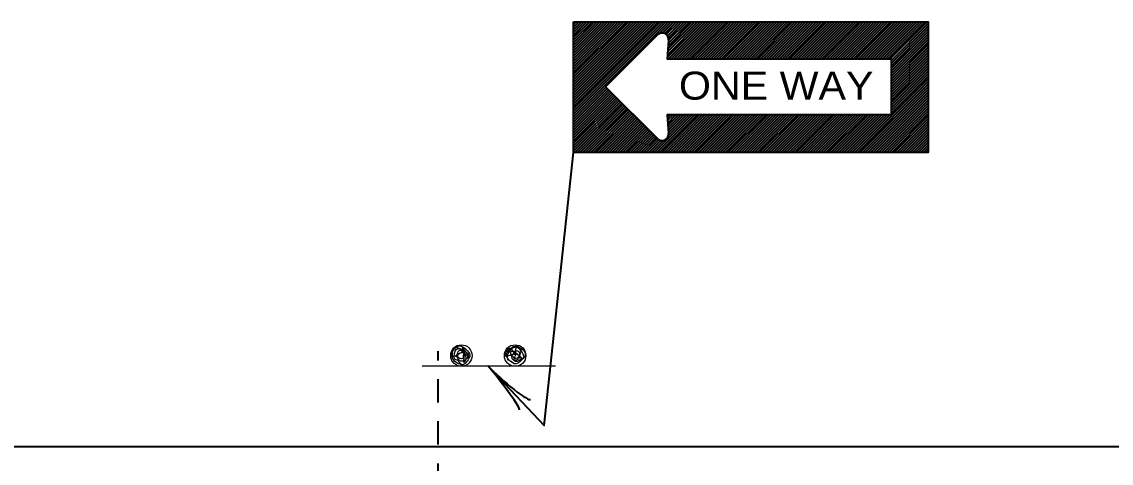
# Model space of a CAD drawing. Extents: x 1081 to 1936, y -630 to -24.
# Drawn here: x 1299 to 1369, y -188.8 to -160.5 of the extents above; entities that cross this region are included whole.
import ezdxf
from ezdxf.enums import TextEntityAlignment as Align

# ---------------------------------------------------------------- set-up
doc = ezdxf.new("R2010")
doc.units = 0
doc.linetypes.add('SHORT_DASHED', pattern=[2.7, 1.5, -1.2])
doc.layers.add('1', color=7, linetype='Continuous', lineweight=53)
doc.layers.add('4', color=7, linetype='Continuous', lineweight=25)

msp = doc.modelspace()

# ---------------------------------------------------------------- linework, layer by layer
at = {"layer": '1', "lineweight": 35}
for p, q in [((1334.418, -160.454), (1334.42, -160.453)), ((1334.418, -160.624), (1334.589, -160.453)), ((1334.418, -160.794), (1334.759, -160.453)), ((1334.418, -160.963), (1334.929, -160.453)), ((1334.418, -161.133), (1335.099, -160.453)), ((1334.418, -161.303), (1335.268, -160.453)), ((1334.418, -161.472), (1335.438, -160.453)), ((1334.418, -161.642), (1335.608, -160.453)), ((1334.418, -161.812), (1335.777, -160.453)), ((1334.418, -161.982), (1335.947, -160.453)), ((1334.418, -162.151), (1336.117, -160.453)), ((1334.418, -162.321), (1336.286, -160.453)), ((1334.418, -162.491), (1336.456, -160.453)), ((1334.418, -162.66), (1336.626, -160.453)), ((1334.418, -162.83), (1336.796, -160.453)), ((1334.418, -163), (1336.965, -160.453)), ((1334.418, -163.169), (1337.135, -160.453)), ((1334.418, -163.339), (1337.305, -160.453)), ((1334.418, -163.509), (1337.474, -160.453)), ((1334.418, -163.679), (1337.644, -160.453)), ((1334.418, -163.848), (1337.814, -160.453)), ((1334.418, -164.018), (1337.984, -160.453)), ((1334.418, -164.188), (1338.153, -160.453)), ((1334.418, -164.357), (1338.323, -160.453)), ((1334.418, -164.527), (1338.493, -160.453)), ((1334.418, -164.697), (1338.662, -160.453)), ((1334.418, -164.867), (1338.832, -160.453)), ((1334.418, -165.036), (1339.002, -160.453)), ((1334.418, -165.206), (1339.171, -160.453)), ((1334.418, -165.376), (1339.341, -160.453)), ((1334.418, -165.545), (1339.511, -160.453)), ((1334.418, -165.715), (1339.681, -160.453)), ((1334.418, -165.885), (1339.85, -160.453)), ((1334.418, -166.054), (1340.02, -160.453)), ((1334.418, -166.224), (1340.19, -160.453)), ((1334.418, -166.394), (1340.359, -160.453)), ((1334.418, -166.564), (1340.529, -160.453)), ((1339.953, -161.198), (1340.699, -160.453)), ((1340.145, -161.176), (1340.869, -160.453)), ((1340.278, -161.213), (1341.038, -160.453)), ((1340.382, -161.278), (1341.208, -160.453)), ((1340.436, -162.752), (1342.735, -160.453)), ((1340.452, -162.566), (1342.566, -160.453)), ((1340.461, -161.369), (1341.378, -160.453)), ((1340.469, -162.38), (1342.396, -160.453)), ((1340.485, -162.194), (1342.226, -160.453)), ((1340.501, -162.008), (1342.056, -160.453)), ((1340.516, -161.484), (1341.547, -160.453)), ((1340.518, -161.822), (1341.887, -160.453)), ((1340.527, -162.831), (1342.905, -160.453)), ((1340.534, -161.636), (1341.717, -160.453)), ((1340.697, -162.831), (1343.075, -160.453)), ((1340.866, -162.831), (1343.244, -160.453)), ((1341.036, -162.831), (1343.414, -160.453)), ((1341.206, -162.831), (1343.584, -160.453)), ((1341.375, -162.831), (1343.754, -160.453)), ((1341.545, -162.831), (1343.923, -160.453)), ((1341.715, -162.831), (1344.093, -160.453)), ((1341.885, -162.831), (1344.263, -160.453)), ((1342.054, -162.831), (1344.432, -160.453)), ((1342.224, -162.831), (1344.602, -160.453)), ((1342.394, -162.831), (1344.772, -160.453)), ((1342.563, -162.831), (1344.941, -160.453)), ((1342.733, -162.831), (1345.111, -160.453)), ((1342.903, -162.831), (1345.281, -160.453)), ((1343.072, -162.831), (1345.451, -160.453)), ((1343.242, -162.831), (1345.62, -160.453)), ((1343.412, -162.831), (1345.79, -160.453)), ((1343.582, -162.831), (1345.96, -160.453)), ((1343.751, -162.831), (1346.129, -160.453)), ((1343.921, -162.831), (1346.299, -160.453)), ((1344.091, -162.831), (1346.469, -160.453)), ((1344.26, -162.831), (1346.639, -160.453)), ((1344.43, -162.831), (1346.808, -160.453)), ((1344.6, -162.831), (1346.978, -160.453)), ((1344.77, -162.831), (1347.148, -160.453)), ((1344.939, -162.831), (1347.317, -160.453)), ((1345.109, -162.831), (1347.487, -160.453)), ((1345.279, -162.831), (1347.657, -160.453)), ((1345.448, -162.831), (1347.826, -160.453)), ((1345.618, -162.831), (1347.996, -160.453)), ((1345.788, -162.831), (1348.166, -160.453)), ((1345.957, -162.831), (1348.336, -160.453)), ((1346.127, -162.831), (1348.505, -160.453)), ((1346.297, -162.831), (1348.675, -160.453)), ((1346.466, -162.831), (1348.845, -160.453)), ((1346.636, -162.831), (1349.014, -160.453)), ((1346.806, -162.831), (1349.184, -160.453)), ((1346.976, -162.831), (1349.354, -160.453)), ((1347.145, -162.831), (1349.524, -160.453)), ((1347.315, -162.831), (1349.693, -160.453)), ((1347.485, -162.831), (1349.863, -160.453)), ((1347.655, -162.831), (1350.033, -160.453)), ((1347.824, -162.831), (1350.202, -160.453)), ((1347.994, -162.831), (1350.372, -160.453)), ((1348.164, -162.831), (1350.542, -160.453)), ((1348.333, -162.831), (1350.711, -160.453)), ((1348.503, -162.831), (1350.881, -160.453)), ((1348.673, -162.831), (1351.051, -160.453)), ((1348.842, -162.831), (1351.221, -160.453)), ((1349.012, -162.831), (1351.39, -160.453)), ((1349.182, -162.831), (1351.56, -160.453)), ((1349.351, -162.831), (1351.73, -160.453)), ((1349.521, -162.831), (1351.899, -160.453)), ((1349.691, -162.831), (1352.069, -160.453)), ((1349.861, -162.831), (1352.239, -160.453)), ((1350.03, -162.831), (1352.409, -160.453)), ((1350.2, -162.831), (1352.578, -160.453)), ((1350.37, -162.831), (1352.748, -160.453)), ((1350.54, -162.831), (1352.918, -160.453)), ((1350.709, -162.831), (1353.087, -160.453)), ((1350.879, -162.831), (1353.257, -160.453)), ((1351.049, -162.831), (1353.427, -160.453)), ((1351.218, -162.831), (1353.596, -160.453)), ((1351.388, -162.831), (1353.766, -160.453)), ((1351.558, -162.831), (1353.936, -160.453)), ((1351.727, -162.831), (1354.106, -160.453)), ((1351.897, -162.831), (1354.275, -160.453)), ((1352.067, -162.831), (1354.445, -160.453)), ((1352.236, -162.831), (1354.615, -160.453)), ((1352.406, -162.831), (1354.784, -160.453)), ((1352.576, -162.831), (1354.954, -160.453)), ((1352.746, -162.831), (1355.124, -160.453)), ((1352.915, -162.831), (1355.293, -160.453)), ((1353.085, -162.831), (1355.463, -160.453)), ((1353.255, -162.831), (1355.633, -160.453)), ((1353.425, -162.831), (1355.803, -160.453)), ((1353.594, -162.831), (1355.972, -160.453)), ((1353.764, -162.831), (1356.142, -160.453)), ((1353.934, -162.831), (1356.312, -160.453)), ((1354.103, -162.831), (1356.481, -160.453)), ((1354.273, -162.831), (1356.651, -160.453)), ((1354.443, -162.831), (1356.821, -160.453)), ((1354.612, -162.831), (1356.991, -160.453)), ((1354.782, -162.831), (1357.16, -160.453)), ((1354.829, -162.953), (1357.218, -160.564)), ((1354.829, -163.123), (1357.218, -160.734)), ((1354.829, -163.293), (1357.218, -160.904)), ((1336.478, -164.631), (1339.872, -161.236)), ((1354.829, -163.462), (1357.218, -161.073)), ((1354.829, -163.632), (1357.218, -161.243)), ((1354.829, -163.802), (1357.218, -161.413)), ((1354.829, -163.972), (1357.218, -161.583)), ((1354.829, -164.141), (1357.218, -161.752)), ((1354.829, -164.311), (1357.218, -161.922)), ((1354.829, -164.481), (1357.218, -162.092)), ((1354.829, -164.65), (1357.218, -162.262)), ((1354.829, -164.82), (1357.218, -162.431)), ((1354.829, -164.99), (1357.218, -162.601)), ((1354.829, -165.159), (1357.218, -162.771)), ((1354.829, -165.329), (1357.218, -162.94)), ((1354.829, -165.499), (1357.218, -163.11)), ((1354.829, -165.668), (1357.218, -163.28)), ((1354.829, -165.838), (1357.218, -163.449)), ((1354.829, -166.008), (1357.218, -163.619)), ((1354.829, -166.178), (1357.218, -163.789)), ((1352.494, -168.853), (1357.218, -164.128)), ((1352.663, -168.853), (1357.218, -164.298)), ((1352.833, -168.853), (1357.218, -164.468)), ((1354.829, -166.347), (1357.218, -163.959)), ((1334.418, -166.733), (1336.499, -164.652)), ((1334.418, -166.903), (1336.584, -164.737)), ((1334.418, -167.073), (1336.669, -164.822)), ((1334.418, -167.242), (1336.754, -164.907)), ((1334.418, -167.412), (1336.839, -164.992)), ((1334.418, -167.582), (1336.923, -165.076)), ((1334.418, -167.752), (1337.008, -165.161)), ((1334.418, -167.921), (1337.093, -165.246)), ((1339.872, -168.025), (1336.478, -164.631)), ((1353.003, -168.853), (1357.218, -164.637)), ((1353.173, -168.853), (1357.218, -164.807)), ((1353.342, -168.853), (1357.218, -164.977)), ((1353.512, -168.853), (1357.218, -165.147)), ((1334.418, -168.091), (1337.178, -165.331)), ((1334.418, -168.261), (1337.263, -165.416)), ((1334.418, -168.43), (1337.348, -165.501)), ((1334.418, -168.6), (1337.433, -165.585)), ((1334.418, -168.77), (1337.517, -165.67)), ((1334.505, -168.853), (1337.602, -165.755)), ((1334.675, -168.853), (1337.687, -165.84)), ((1334.844, -168.853), (1337.772, -165.925)), ((1353.682, -168.853), (1357.218, -165.316)), ((1353.851, -168.853), (1357.218, -165.486)), ((1354.021, -168.853), (1357.218, -165.656)), ((1354.191, -168.853), (1357.218, -165.825)), ((1335.014, -168.853), (1337.857, -166.01)), ((1335.184, -168.853), (1337.942, -166.095)), ((1335.354, -168.853), (1338.027, -166.179)), ((1335.523, -168.853), (1338.111, -166.264)), ((1335.693, -168.853), (1338.196, -166.349)), ((1335.863, -168.853), (1338.281, -166.434)), ((1336.032, -168.853), (1338.366, -166.519)), ((1336.202, -168.853), (1338.451, -166.604)), ((1339.596, -168.853), (1342.018, -166.431)), ((1339.766, -168.853), (1342.188, -166.431)), ((1339.936, -168.853), (1342.357, -166.431)), ((1340.105, -168.853), (1342.527, -166.431)), ((1340.275, -168.853), (1342.697, -166.431)), ((1340.434, -166.487), (1340.491, -166.431)), ((1340.445, -168.853), (1342.867, -166.431)), ((1340.448, -166.643), (1340.66, -166.431)), ((1340.462, -166.799), (1340.83, -166.431)), ((1340.475, -166.955), (1341, -166.431)), ((1340.489, -167.111), (1341.169, -166.431)), ((1340.502, -167.267), (1341.339, -166.431)), ((1340.516, -167.423), (1341.509, -166.431)), ((1340.521, -167.758), (1341.848, -166.431)), ((1340.53, -167.579), (1341.679, -166.431)), ((1340.614, -168.853), (1343.036, -166.431)), ((1340.784, -168.853), (1343.206, -166.431)), ((1340.954, -168.853), (1343.376, -166.431)), ((1341.124, -168.853), (1343.545, -166.431)), ((1341.293, -168.853), (1343.715, -166.431)), ((1341.463, -168.853), (1343.885, -166.431)), ((1341.633, -168.853), (1344.054, -166.431)), ((1341.802, -168.853), (1344.224, -166.431)), ((1341.972, -168.853), (1344.394, -166.431)), ((1342.142, -168.853), (1344.564, -166.431)), ((1342.311, -168.853), (1344.733, -166.431)), ((1342.481, -168.853), (1344.903, -166.431)), ((1342.651, -168.853), (1345.073, -166.431)), ((1342.821, -168.853), (1345.242, -166.431)), ((1342.99, -168.853), (1345.412, -166.431)), ((1343.16, -168.853), (1345.582, -166.431)), ((1343.33, -168.853), (1345.752, -166.431)), ((1343.499, -168.853), (1345.921, -166.431)), ((1343.669, -168.853), (1346.091, -166.431)), ((1343.839, -168.853), (1346.261, -166.431)), ((1344.009, -168.853), (1346.43, -166.431)), ((1344.178, -168.853), (1346.6, -166.431)), ((1344.348, -168.853), (1346.77, -166.431)), ((1344.518, -168.853), (1346.939, -166.431)), ((1344.687, -168.853), (1347.109, -166.431)), ((1344.857, -168.853), (1347.279, -166.431)), ((1345.027, -168.853), (1347.449, -166.431)), ((1345.196, -168.853), (1347.618, -166.431)), ((1345.366, -168.853), (1347.788, -166.431)), ((1345.536, -168.853), (1347.958, -166.431)), ((1345.706, -168.853), (1348.127, -166.431)), ((1345.875, -168.853), (1348.297, -166.431)), ((1346.045, -168.853), (1348.467, -166.431)), ((1346.215, -168.853), (1348.637, -166.431)), ((1346.384, -168.853), (1348.806, -166.431)), ((1346.554, -168.853), (1348.976, -166.431)), ((1346.724, -168.853), (1349.146, -166.431)), ((1346.894, -168.853), (1349.315, -166.431)), ((1347.063, -168.853), (1349.485, -166.431)), ((1347.233, -168.853), (1349.655, -166.431)), ((1347.403, -168.853), (1349.825, -166.431)), ((1347.572, -168.853), (1349.994, -166.431)), ((1347.742, -168.853), (1350.164, -166.431)), ((1347.912, -168.853), (1350.334, -166.431)), ((1348.081, -168.853), (1350.503, -166.431)), ((1348.251, -168.853), (1350.673, -166.431)), ((1348.421, -168.853), (1350.843, -166.431)), ((1348.591, -168.853), (1351.012, -166.431)), ((1348.76, -168.853), (1351.182, -166.431)), ((1348.93, -168.853), (1351.352, -166.431)), ((1349.1, -168.853), (1351.522, -166.431)), ((1349.269, -168.853), (1351.691, -166.431)), ((1349.439, -168.853), (1351.861, -166.431)), ((1349.609, -168.853), (1352.031, -166.431)), ((1349.778, -168.853), (1352.2, -166.431)), ((1349.948, -168.853), (1352.37, -166.431)), ((1350.118, -168.853), (1352.54, -166.431)), ((1350.288, -168.853), (1352.71, -166.431)), ((1350.457, -168.853), (1352.879, -166.431)), ((1350.627, -168.853), (1353.049, -166.431)), ((1350.797, -168.853), (1353.219, -166.431)), ((1350.966, -168.853), (1353.388, -166.431)), ((1351.136, -168.853), (1353.558, -166.431)), ((1351.306, -168.853), (1353.728, -166.431)), ((1351.476, -168.853), (1353.897, -166.431)), ((1351.645, -168.853), (1354.067, -166.431)), ((1351.815, -168.853), (1354.237, -166.431)), ((1351.985, -168.853), (1354.407, -166.431)), ((1352.154, -168.853), (1354.576, -166.431)), ((1352.324, -168.853), (1354.746, -166.431)), ((1354.361, -168.853), (1357.218, -165.995)), ((1354.53, -168.853), (1357.218, -166.165)), ((1354.7, -168.853), (1357.218, -166.334)), ((1354.87, -168.853), (1357.218, -166.504)), ((1336.372, -168.853), (1338.536, -166.689)), ((1336.541, -168.853), (1338.62, -166.773)), ((1336.711, -168.853), (1338.705, -166.858)), ((1336.881, -168.853), (1338.79, -166.943)), ((1337.051, -168.853), (1338.875, -167.028)), ((1337.22, -168.853), (1338.96, -167.113)), ((1337.39, -168.853), (1339.045, -167.198)), ((1337.56, -168.853), (1339.13, -167.282)), ((1355.039, -168.853), (1357.218, -166.674)), ((1355.209, -168.853), (1357.218, -166.844)), ((1355.379, -168.853), (1357.218, -167.013)), ((1355.548, -168.853), (1357.218, -167.183)), ((1355.718, -168.853), (1357.218, -167.353)), ((1337.729, -168.853), (1339.215, -167.367)), ((1337.899, -168.853), (1339.299, -167.452)), ((1338.069, -168.853), (1339.384, -167.537)), ((1338.239, -168.853), (1339.469, -167.622)), ((1338.408, -168.853), (1339.554, -167.707)), ((1338.578, -168.853), (1339.639, -167.792)), ((1338.748, -168.853), (1339.724, -167.877)), ((1338.917, -168.853), (1339.808, -167.961)), ((1339.087, -168.853), (1339.899, -168.04)), ((1355.888, -168.853), (1357.218, -167.522)), ((1356.058, -168.853), (1357.218, -167.692)), ((1356.227, -168.853), (1357.218, -167.862)), ((1356.397, -168.853), (1357.218, -168.031)), ((1339.257, -168.853), (1340.027, -168.082)), ((1339.426, -168.853), (1340.204, -168.075)), ((1356.567, -168.853), (1357.218, -168.201)), ((1356.736, -168.853), (1357.218, -168.371)), ((1356.906, -168.853), (1357.218, -168.541)), ((1357.076, -168.853), (1357.218, -168.71))]:
    msp.add_line(p, q, dxfattribs=at)
at = {"layer": '1', "linetype": 'SHORT_DASHED', "lineweight": 35}
msp.add_line((1325.717, -220.021), (1325.717, -181.62), dxfattribs=at)
at = {"layer": '1', "lineweight": 25}
msp.add_line((1324.701, -182.556), (1333.269, -182.556), dxfattribs=at)
at = {"layer": '1', "lineweight": 40}
msp.add_line((1159.75, -187.749), (1403.89, -187.749), dxfattribs=at)
at = {"layer": '1', "lineweight": 35}
msp.add_lwpolyline([(1334.418, -160.453), (1357.218, -160.453), (1357.218, -168.853), (1334.418, -168.853)], close=True, dxfattribs=at)
for points in [[(1340.534, -161.635), (1340.429, -162.831), (1354.829, -162.831), (1354.829, -166.431), (1340.429, -166.431), (1340.534, -167.626)], [(1328.917, -182.556), (1332.543, -186.398), (1334.418, -168.853)]]:
    msp.add_lwpolyline(points, dxfattribs=at)
for centre, start, end in [((1340.098, -161.61), 356.63551, 121.23355), ((1340.098, -167.652), 238.76645, 3.36449)]:
    msp.add_arc(centre, 0.436, start, end, dxfattribs=at)
at = {"layer": '1', "lineweight": 40}
for centre, major_axis, ratio, start_param, end_param in [((1329.655, -183.708), (-1.293, 1.678), 0.07063, 3.140715, 5.41811), ((1330.057, -183.281), (-1.607, 1.43), 0.122415, 0.896353, 3.141593)]:
    msp.add_ellipse(centre, major_axis=major_axis, ratio=ratio, start_param=start_param, end_param=end_param, dxfattribs=at)
at = {"layer": '1', "lineweight": 25}
for points in [[(1327.221, -182.489), (1326.851, -182.321), (1326.616, -181.951), (1326.683, -181.548), (1327.12, -181.279), (1327.523, -181.514), (1327.758, -181.85), (1327.691, -182.085), (1327.221, -182.489), (1326.986, -182.22), (1326.784, -182.119), (1326.75, -181.918), (1326.986, -181.447), (1327.221, -181.481), (1327.389, -181.615), (1327.658, -181.783), (1327.456, -182.186), (1327.187, -182.254), (1327.019, -182.119), (1326.918, -181.918), (1326.986, -181.716), (1327.053, -181.582), (1327.389, -181.682), (1327.322, -181.918), (1327.322, -182.052), (1327.053, -182.052), (1326.986, -181.85), (1327.355, -181.716), (1327.422, -181.75), (1327.725, -182.052), (1327.288, -181.413), (1327.389, -181.716), (1326.885, -181.38), (1326.65, -181.951), (1327.355, -181.716), (1327.389, -182.321), (1327.49, -182.186), (1327.355, -181.716)], [(1330.614, -182.422), (1330.278, -182.186), (1330.11, -181.85), (1330.211, -181.615), (1330.581, -181.38), (1330.95, -181.38), (1331.32, -181.75), (1331.085, -182.186), (1330.614, -182.422), (1330.413, -182.287), (1330.245, -182.186), (1330.178, -181.884), (1330.413, -181.481), (1330.547, -181.313), (1331.018, -181.582), (1330.95, -181.918), (1330.883, -182.119), (1330.749, -182.186), (1330.547, -182.186), (1330.446, -181.985), (1330.413, -181.615), (1330.648, -181.615), (1330.816, -181.582), (1330.95, -181.783), (1330.715, -182.085), (1330.514, -181.951), (1330.48, -181.817), (1330.715, -181.783), (1330.682, -181.716), (1331.186, -182.085), (1330.749, -181.279), (1330.648, -181.75), (1330.346, -181.447), (1330.01, -181.918), (1330.715, -181.783), (1330.581, -182.22), (1331.051, -182.119), (1330.715, -181.783)]]:
    msp.add_spline(points, degree=3, dxfattribs=at)
at = {"layer": '4'}
for centre in [(1327.213, -181.895), (1330.668, -181.895)]:
    msp.add_circle(centre, 0.689, dxfattribs=at)

# ---------------------------------------------------------------- texts
at = {"layer": '1', "width": 1.1}
msp.add_text('ONE WAY', height=1.8, dxfattribs=at).set_placement((1347.446, -165.454), align=Align.CENTER)

doc.saveas('drawing.dxf')
